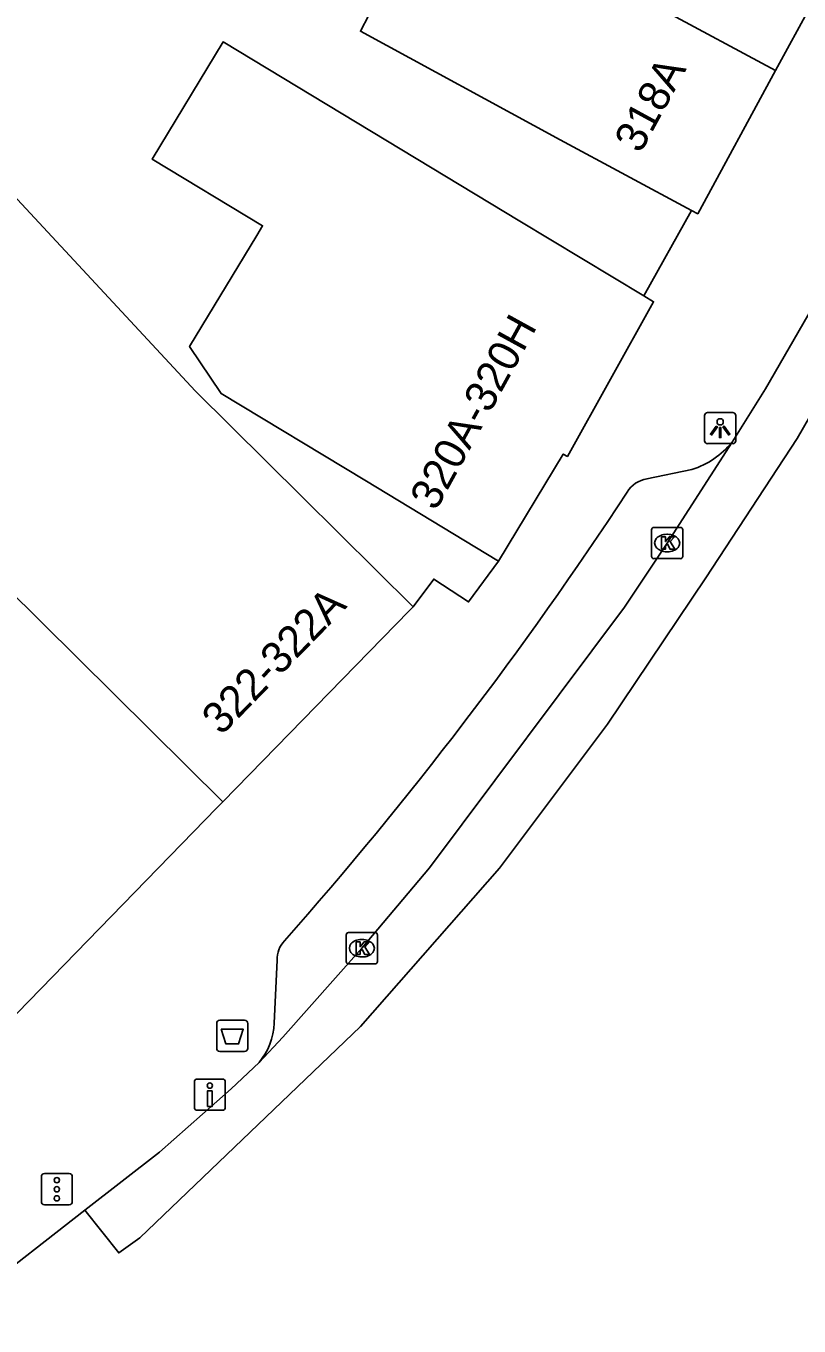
# Model space of a CAD drawing. Extents: x 159222 to 160346, y 381249 to 382166.
# Drawn here: x 160163.43 to 160188.17, y 381633.34 to 381674.92 of the extents above; entities that cross this region are included whole.
import ezdxf

# ---------------------------------------------------------------- set-up
doc = ezdxf.new("R2010")
doc.units = 0
for name, color, linetype in [('IMGEO_Afvalbak', 7, 'Continuous'), ('IMGEO_Drukknoppaal', 7, 'Continuous'), ('IMGEO_Kolk', 7, 'Continuous'), ('IMGEO_Lichtpunt', 7, 'Continuous'), ('IMGEO_Muur', 7, 'Continuous'), ('IMGEO_Pand', 7, 'Continuous'), ('IMGEO_Pand_nummerreeks', 7, 'Continuous'), ('IMGEO_Rijbaan_lokaal_gesloten', 7, 'Continuous'), ('IMGEO_Verkeersregelinstallatiepaal', 7, 'Continuous'), ('IMGEO_Voetpad_open', 7, 'Continuous')]:
    doc.layers.add(name, color=color, linetype=linetype)

msp = doc.modelspace()

# ---------------------------------------------------------------- linework, layer by layer
at = {"layer": 'IMGEO_Afvalbak'}
for p, q in [((160169.632, 381643.116), (160170.422, 381643.116)), ((160170.422, 381643.116), (160169.632, 381643.116)), ((160169.532, 381642.216), (160169.532, 381643.016)), ((160169.532, 381643.016), (160169.532, 381642.216)), ((160170.522, 381643.016), (160170.522, 381642.216)), ((160170.522, 381642.216), (160170.522, 381643.016)), ((160170.422, 381642.116), (160169.632, 381642.116)), ((160169.632, 381642.116), (160170.422, 381642.116))]:
    msp.add_line(p, q, dxfattribs=at)
msp.add_lwpolyline([(160169.675, 381642.83), (160170.379, 381642.83), (160170.23, 381642.36), (160169.824, 381642.36), (160169.675, 381642.83)], dxfattribs=at)
for centre, start, end in [((160169.632, 381643.016), 90, 180), ((160169.632, 381643.016), 90, 180), ((160170.422, 381643.016), 0, 90), ((160170.422, 381643.016), 360, 90), ((160169.632, 381642.216), 180, 270), ((160169.632, 381642.216), 180, 270), ((160170.422, 381642.216), 270, 0), ((160170.422, 381642.216), 270, 0)]:
    msp.add_arc(centre, 0.1, start, end, dxfattribs=at)
at = {"layer": 'IMGEO_Drukknoppaal'}
for p, q in [((160168.817, 381640.335), (160168.817, 381641.135)), ((160168.817, 381641.135), (160168.817, 381640.335)), ((160168.917, 381641.235), (160169.707, 381641.235)), ((160169.707, 381641.235), (160168.917, 381641.235)), ((160169.807, 381641.135), (160169.807, 381640.335)), ((160169.807, 381640.335), (160169.807, 381641.135)), ((160169.707, 381640.235), (160168.917, 381640.235)), ((160168.917, 381640.235), (160169.707, 381640.235))]:
    msp.add_line(p, q, dxfattribs=at)
msp.add_lwpolyline([(160169.387, 381640.86), (160169.387, 381640.36), (160169.237, 381640.36), (160169.237, 381640.86), (160169.387, 381640.86)], dxfattribs=at)
msp.add_circle((160169.312, 381641.025), 0.085, dxfattribs=at)
for centre, start, end in [((160168.917, 381641.135), 90, 180), ((160168.917, 381641.135), 90, 180), ((160169.707, 381641.135), 0, 90), ((160169.707, 381641.135), 360, 90), ((160168.917, 381640.335), 180, 270), ((160168.917, 381640.335), 180, 270), ((160169.707, 381640.335), 270, 0), ((160169.707, 381640.335), 270, 0)]:
    msp.add_arc(centre, 0.1, start, end, dxfattribs=at)
at = {"layer": 'IMGEO_Kolk'}
for p, q in [((160183.448, 381657.957), (160183.448, 381658.809)), ((160183.523, 381658.883), (160184.375, 381658.883)), ((160183.936, 381658.663), (160183.961, 381658.663)), ((160184.449, 381658.809), (160184.449, 381657.957)), ((160183.959, 381658.103), (160183.934, 381658.103)), ((160184.375, 381657.883), (160183.523, 381657.883)), ((160173.676, 381644.994), (160173.676, 381645.846)), ((160173.751, 381645.92), (160174.603, 381645.92)), ((160174.164, 381645.7), (160174.189, 381645.7)), ((160174.677, 381645.846), (160174.677, 381644.994)), ((160174.603, 381644.92), (160173.751, 381644.92)), ((160174.187, 381645.14), (160174.162, 381645.14))]:
    msp.add_line(p, q, dxfattribs=at)
for points in [[(160183.448, 381657.957), (160183.448, 381658.809)], [(160183.523, 381658.883), (160184.375, 381658.883)], [(160183.769, 381658.583), (160183.892, 381658.583), (160183.892, 381658.432), (160184.022, 381658.583), (160184.186, 381658.583), (160184.04, 381658.432), (160184.193, 381658.183), (160184.041, 381658.183), (160183.956, 381658.347), (160183.892, 381658.28), (160183.892, 381658.183), (160183.769, 381658.183), (160183.769, 381658.583)], [(160184.449, 381658.809), (160184.449, 381657.957)], [(160184.375, 381657.883), (160183.523, 381657.883)], [(160173.676, 381644.994), (160173.676, 381645.846)], [(160173.751, 381645.92), (160174.603, 381645.92)], [(160173.997, 381645.62), (160174.12, 381645.62), (160174.12, 381645.469), (160174.25, 381645.62), (160174.414, 381645.62), (160174.268, 381645.469), (160174.421, 381645.22), (160174.269, 381645.22), (160174.184, 381645.384), (160174.12, 381645.317), (160174.12, 381645.22), (160173.997, 381645.22), (160173.997, 381645.62)], [(160174.677, 381645.846), (160174.677, 381644.994)], [(160174.603, 381644.92), (160173.751, 381644.92)]]:
    msp.add_lwpolyline(points, dxfattribs=at)
for centre, start, end in [((160183.525, 381658.807), 91.552, 178.448), ((160183.525, 381658.807), 91.552, 178.448), ((160184.373, 381658.807), 1.552, 88.448), ((160184.373, 381658.807), 1.552, 88.448), ((160183.525, 381657.959), 181.552, 268.448), ((160183.525, 381657.959), 181.552, 268.448), ((160184.373, 381657.959), 271.552, 358.448), ((160184.373, 381657.959), 271.552, 358.448), ((160173.753, 381645.844), 91.552, 178.448), ((160173.753, 381645.844), 91.552, 178.448), ((160174.601, 381645.844), 1.552, 88.448), ((160174.601, 381645.844), 1.552, 88.448), ((160173.753, 381644.996), 181.552, 268.448), ((160173.753, 381644.996), 181.552, 268.448), ((160174.601, 381644.996), 271.552, 358.448), ((160174.601, 381644.996), 271.552, 358.448)]:
    msp.add_arc(centre, 0.0765, start, end, dxfattribs=at)
for centre, major_axis, ratio, start_param, end_param in [((160183.935, 381658.383), (-0.387, 0.002), 0.722429, 4.712389, 7.853982), ((160183.96, 381658.383), (-0.39, 0.002), 0.717154, 1.570796, 4.712389), ((160174.163, 381645.42), (-0.387, 0.002), 0.722429, 4.712389, 7.853982), ((160174.188, 381645.42), (-0.39, 0.002), 0.717154, 1.570796, 4.712389)]:
    msp.add_ellipse(centre, major_axis=major_axis, ratio=ratio, start_param=start_param, end_param=end_param, dxfattribs=at)
at = {"layer": 'IMGEO_Lichtpunt'}
for p, q in [((160185.146, 381662.463), (160185.146, 381661.656)), ((160185.146, 381662.463), (160185.146, 381661.656)), ((160186.048, 381662.558), (160185.24, 381662.558)), ((160186.048, 381662.558), (160185.24, 381662.558)), ((160186.142, 381661.656), (160186.142, 381662.463)), ((160186.142, 381661.656), (160186.142, 381662.463)), ((160185.24, 381661.562), (160186.048, 381661.562)), ((160185.24, 381661.562), (160186.048, 381661.562))]:
    msp.add_line(p, q, dxfattribs=at)
for points in [[(160185.52, 381662.127), (160185.559, 381662.099), (160185.371, 381661.837), (160185.333, 381661.864), (160185.52, 381662.127)], [(160185.622, 381662.079), (160185.669, 381662.079), (160185.669, 381661.757), (160185.622, 381661.757), (160185.622, 381662.079)], [(160185.732, 381662.099), (160185.77, 381662.126), (160185.957, 381661.864), (160185.918, 381661.836), (160185.732, 381662.099)]]:
    msp.add_lwpolyline(points, dxfattribs=at)
msp.add_circle((160185.645, 381662.261), 0.0994, dxfattribs=at)
for centre, start, end in [((160185.24, 381662.463), 90, 180), ((160185.24, 381662.463), 90, 180), ((160186.048, 381662.463), 0, 90), ((160186.048, 381662.463), 0, 90), ((160185.24, 381661.656), 180, 270), ((160185.24, 381661.656), 180, 270), ((160186.048, 381661.656), 270, 0), ((160186.048, 381661.656), 270, 360)]:
    msp.add_arc(centre, 0.0946, start, end, dxfattribs=at)
at = {"layer": 'IMGEO_Muur'}
msp.add_lwpolyline([(160175.82, 381656.347), (160176.476, 381657.23), (160177.594, 381656.498), (160178.547, 381657.806)], dxfattribs=at)
at = {"layer": 'IMGEO_Pand'}
for points in [[(160187.416, 381673.501), (160176.563, 381679.334)], [(160189.812, 381677.911), (160189.695, 381677.696), (160187.416, 381673.501)], [(160155.774, 381677.313), (160168.856, 381663.241), (160172.267, 381659.865), (160175.82, 381656.347)], [(160174.403, 381675.265), (160174.132, 381674.754), (160180.523, 381671.287), (160184.732, 381669.023)], [(160183.198, 381666.291), (160179.235, 381668.683), (160169.735, 381674.416), (160167.469, 381670.662), (160170.999, 381668.533), (160170.81, 381668.22), (160168.665, 381664.666), (160169.673, 381663.162), (160174.267, 381660.389), (160178.547, 381657.806)], [(160187.416, 381673.501), (160184.926, 381668.919), (160184.732, 381669.023)], [(160183.198, 381666.291), (160183.515, 381666.1), (160180.755, 381661.156), (160180.621, 381661.226), (160178.547, 381657.806)], [(160169.728, 381650.105), (160154.626, 381665.044)], [(160175.82, 381656.347), (160175.686, 381656.21), (160169.728, 381650.105)], [(160169.728, 381650.105), (160169.539, 381649.911), (160156.005, 381636.02)]]:
    msp.add_lwpolyline(points, dxfattribs=at)
at = {"layer": 'IMGEO_Rijbaan_lokaal_gesloten'}
for points in [[(160214.17, 381712.699), (160209.297, 381702.977), (160200.237, 381684.926), (160195.4, 381675.172), (160192.483, 381669.642), (160190.409, 381665.724), (160188.106, 381661.73), (160185.188, 381657.275), (160182.04, 381652.59), (160178.585, 381647.981), (160174.132, 381642.912), (160167.068, 381636.152), (160166.394, 381635.674), (160165.31, 381637.041)], [(160186.026, 381661.61), (160187.091, 381663.311), (160189.363, 381667.254), (160190.145, 381668.66), (160190.792, 381669.884), (160193.671, 381675.387), (160195.585, 381679.238), (160197.363, 381682.824), (160199.383, 381686.888)], [(160186.026, 381661.61), (160183.946, 381658.383), (160182.579, 381656.327), (160176.347, 381647.994), (160174.174, 381645.419), (160171.648, 381642.571), (160170.885, 381641.766)], [(160165.31, 381637.041), (160167.695, 381638.896), (160169.991, 381640.927), (160170.885, 381641.766)], [(160165.31, 381637.041), (160161.833, 381634.337), (160160.845, 381633.624), (160160.612, 381633.458), (160160.414, 381633.335)]]:
    msp.add_lwpolyline(points, dxfattribs=at)
at = {"layer": 'IMGEO_Verkeersregelinstallatiepaal'}
for p, q in [((160164.019, 381638.209), (160164.809, 381638.209)), ((160164.809, 381638.209), (160164.019, 381638.209)), ((160163.919, 381637.309), (160163.919, 381638.109)), ((160163.919, 381638.109), (160163.919, 381637.309)), ((160164.909, 381638.109), (160164.909, 381637.309)), ((160164.909, 381637.309), (160164.909, 381638.109)), ((160164.809, 381637.209), (160164.019, 381637.209)), ((160164.019, 381637.209), (160164.809, 381637.209))]:
    msp.add_line(p, q, dxfattribs=at)
for centre in [(160164.414, 381637.999), (160164.414, 381637.709), (160164.414, 381637.419)]:
    msp.add_circle(centre, 0.085, dxfattribs=at)
for centre, start, end in [((160164.019, 381638.109), 90, 180), ((160164.019, 381638.109), 90, 180), ((160164.809, 381638.109), 0, 90), ((160164.809, 381638.109), 360, 90), ((160164.019, 381637.309), 180, 270), ((160164.019, 381637.309), 180, 270), ((160164.809, 381637.309), 270, 0), ((160164.809, 381637.309), 270, 0)]:
    msp.add_arc(centre, 0.1, start, end, dxfattribs=at)
at = {"layer": 'IMGEO_Voetpad_open'}
for points in [[(160184.732, 381669.023), (160183.198, 381666.291)], [(160183.303, 381660.438), (160184.742, 381660.731)], [(160178.547, 381657.806), (160177.594, 381656.498), (160176.476, 381657.23), (160175.82, 381656.347)], [(160171.366, 381643.023), (160171.463, 381645.041)]]:
    msp.add_lwpolyline(points, dxfattribs=at)
for centre, radius, start, end in [((160183.887, 381663.357), 2.761, 288.0295, 320.76), ((160183.444, 381659.545), 0.904, 98.9605, 148.9602), ((160077.804, 381728.79), 125.408, 318.47899, 326.73964), ((160172.346, 381645.057), 0.883, 137.11, 181.0267), ((160169.344, 381643.076), 2.023, 319.6266, 358.494)]:
    msp.add_arc(centre, radius, start, end, dxfattribs=at)

# ---------------------------------------------------------------- texts
at = {"layer": 'IMGEO_Pand_nummerreeks'}
for s, rotation, p in [('318A', 61.4784, (160183.09, 381670.816)), ('320A-320H', 61.2034, (160176.544, 381659.379)), ('322-322A', 45.6991, (160169.68, 381652.203))]:
    msp.add_text(s, height=1, rotation=rotation, dxfattribs=at).set_placement(p)

doc.saveas('drawing.dxf')
